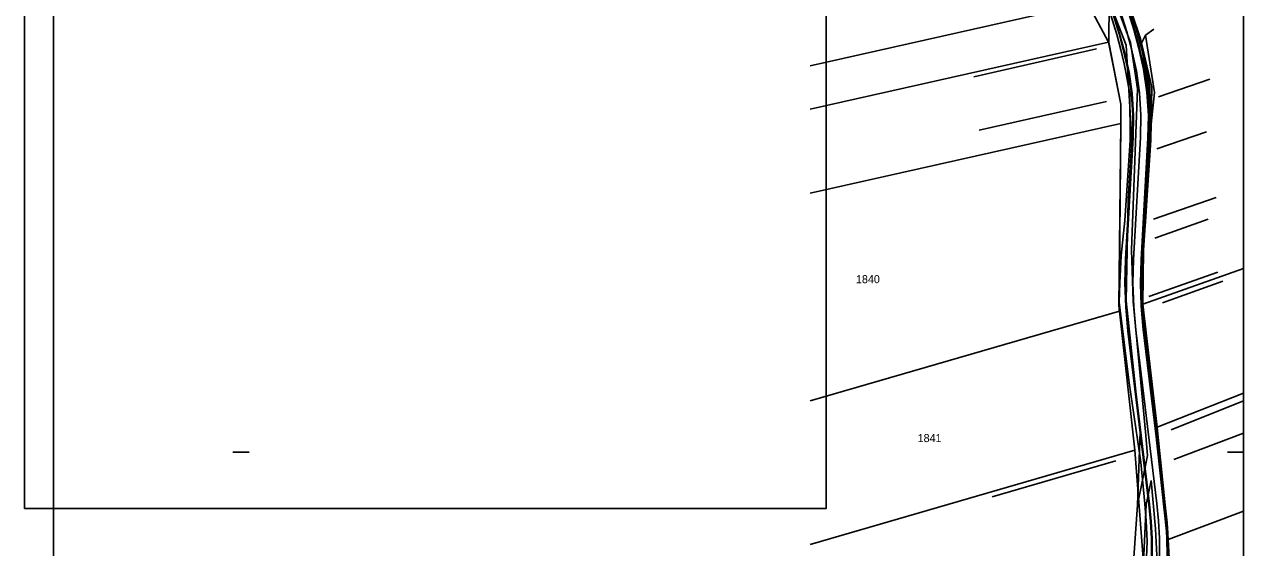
# Model space of a CAD drawing. Extents: x -601800 to -601487, y -1201912 to -1200862.
# Drawn here: x -601790.9 to -601486.7, y -1201516.2 to -1201385.7 of the extents above; entities that cross this region are included whole.
import ezdxf

# ---------------------------------------------------------------- set-up
doc = ezdxf.new("R2010")
doc.units = 0
for name, color, linetype in [('Hranice parcel', 7, 'Continuous'), ('Parcelní čísla', 7, 'Continuous'), ('u_hrany', 7, 'Continuous'), ('u_návrh', 7, 'Continuous'), ('u_osa', 7, 'Continuous'), ('u_strom', 7, 'Continuous'), ('u_terénní úpravy', 7, 'Continuous'), ('x_rám', 7, 'Continuous')]:
    doc.layers.add(name, color=color, linetype=linetype)

msp = doc.modelspace()

# ---------------------------------------------------------------- linework, layer by layer
at = {"layer": 'Hranice parcel'}
for p, q in [((-601594.83, -1201396.03), (-601525.57, -1201380.51)), ((-601525.57, -1201380.51), (-601520.35, -1201390.13)), ((-601594.83, -1201406.82), (-601520.35, -1201390.13)), ((-601594.83, -1201427.76), (-601517.31, -1201410.46)), ((-601594.83, -1201479.55), (-601517.67, -1201457.2)), ((-601517.67, -1201457.2), (-601513.82, -1201491.91)), ((-601508.25, -1201486.13), (-601511.82, -1201455.51)), ((-601594.83, -1201515.38), (-601513.82, -1201491.91)), ((-601513.82, -1201491.91), (-601511.75, -1201518.89)), ((-601486.66, -1201507.11), (-601505.47, -1201514.18))]:
    msp.add_line(p, q, dxfattribs=at)
for points in [[(-601511.82, -1201455.51), (-601511.63, -1201442.04), (-601509.82, -1201414.6), (-601509.57, -1201401.34), (-601512.41, -1201389.28), (-601514.66, -1201382.62)], [(-601520.35, -1201390.13), (-601517.26, -1201405.61), (-601517.31, -1201410.46)], [(-601517.31, -1201410.46), (-601517.81, -1201455.91), (-601517.67, -1201457.2)], [(-601486.66, -1201446.59), (-601511.82, -1201455.51)], [(-601486.66, -1201477.68), (-601508.25, -1201486.13)], [(-601505.47, -1201514.18), (-601505.62, -1201511.23), (-601508.14, -1201487.04), (-601508.25, -1201486.13)], [(-601504.99, -1201526.96), (-601504.94, -1201524.87), (-601505.47, -1201514.18)]]:
    msp.add_lwpolyline(points, dxfattribs=at)
at = {"layer": 'u_hrany'}
for points in [[(-601510.66, -1201493.25), (-601511.13, -1201487.34), (-601514.2, -1201454.81), (-601514.64, -1201441.92), (-601513.13, -1201401.75), (-601514.86, -1201390.2), (-601518.87, -1201379.54), (-601520.9, -1201374.92)], [(-601517.26, -1201405.61), (-601520.32, -1201390.19), (-601520.24, -1201380), (-601515.97, -1201390.87)], [(-601512.26, -1201390.52), (-601511.11, -1201388.4), (-601509.06, -1201386.94)], [(-601510.09, -1201413.72), (-601508.92, -1201402.68), (-601511.11, -1201388.4)], [(-601515.97, -1201390.87), (-601514.58, -1201414.64), (-601515.47, -1201429.34), (-601515.96, -1201454.63), (-601512.47, -1201487.32), (-601513.15, -1201505.52)], [(-601512.26, -1201390.52), (-601510.47, -1201401.41), (-601510.09, -1201413.72), (-601511.79, -1201441.97), (-601511.82, -1201455.52), (-601508.66, -1201487.01), (-601505.94, -1201512.07), (-601505.14, -1201523.95), (-601505.37, -1201547.09), (-601506.1, -1201561.67), (-601507, -1201580.71), (-601507.44, -1201612.51), (-601506.59, -1201624.18), (-601504.84, -1201632.93)], [(-601523.39, -1201391.84), (-601553.96, -1201398.76)], [(-601507.87, -1201403.76), (-601495.07, -1201399.33)], [(-601520.87, -1201404.96), (-601552.65, -1201412.05)], [(-601517.26, -1201410.36), (-601517.73, -1201457.2)], [(-601508.3, -1201416.7), (-601495.96, -1201412.46)], [(-601509.14, -1201434.24), (-601493.54, -1201428.85)], [(-601508.78, -1201439.01), (-601495.5, -1201434.28)], [(-601510.28, -1201453.55), (-601493.09, -1201447.49)], [(-601506.87, -1201455.17), (-601491.82, -1201449.78)], [(-601504.71, -1201486.78), (-601486.66, -1201479.62)], [(-601504.1, -1201494.18), (-601486.66, -1201487.68)], [(-601518.55, -1201494.53), (-601549.39, -1201503.49)], [(-601510.66, -1201493.25), (-601513.15, -1201505.52)], [(-601511, -1201505.42), (-601509.72, -1201499.44)], [(-601509.48, -1201566.66), (-601507.81, -1201547.43), (-601507.95, -1201524.83), (-601508.61, -1201511.46), (-601509.72, -1201499.44)], [(-601514.34, -1201522.2), (-601513.15, -1201505.52)], [(-601511, -1201505.42), (-601511.8, -1201523.53)]]:
    msp.add_lwpolyline(points, dxfattribs=at)
at = {"layer": 'u_návrh'}
for points in [[(-601553.14, -1201317.8), (-601552.81, -1201318.66), (-601546.01, -1201333.72), (-601538.39, -1201348.39), (-601530, -1201362.6), (-601525.72, -1201369.43), (-601523.16, -1201373.86), (-601520.96, -1201378.43), (-601519.1, -1201383.16), (-601517.59, -1201388.04), (-601516.46, -1201392.25), (-601515.25, -1201397.59), (-601514.48, -1201402.97), (-601514.13, -1201408.4), (-601514.23, -1201413.88), (-601515.96, -1201444.23), (-601516.12, -1201450.21), (-601515.93, -1201456.22), (-601515.39, -1201462.18), (-601510.17, -1201505.36), (-601509.75, -1201509.65), (-601509.52, -1201513.93), (-601509.47, -1201518.24), (-601509.71, -1201540.62)], [(-601549.75, -1201316.3), (-601549.39, -1201317.23), (-601542.68, -1201332.11), (-601535.16, -1201346.59), (-601526.84, -1201360.67), (-601522.55, -1201367.52), (-601519.89, -1201372.13), (-601517.56, -1201376.95), (-601515.6, -1201381.93), (-601514.03, -1201387.02), (-601512.87, -1201391.36), (-601511.61, -1201396.91), (-601510.79, -1201402.59), (-601510.43, -1201408.32), (-601510.53, -1201414.01), (-601512.26, -1201444.39), (-601512.42, -1201450.21), (-601512.24, -1201456), (-601511.71, -1201461.79), (-601506.5, -1201504.96), (-601506.06, -1201509.37), (-601505.82, -1201513.81), (-601505.77, -1201518.24), (-601506.19, -1201556.5)], [(-601515.46, -1201381.89), (-601513.89, -1201386.98), (-601512.72, -1201391.32), (-601511.46, -1201396.89), (-601510.64, -1201402.58), (-601510.28, -1201408.31), (-601510.38, -1201414.02), (-601512.11, -1201444.4), (-601512.27, -1201450.21), (-601512.09, -1201455.99), (-601511.56, -1201461.78), (-601506.35, -1201504.94), (-601505.91, -1201509.36), (-601505.67, -1201513.81), (-601505.62, -1201518.24), (-601506.04, -1201556.51)], [(-601519.24, -1201383.21), (-601517.73, -1201388.09), (-601516.61, -1201392.28), (-601515.4, -1201397.61), (-601514.63, -1201402.99), (-601514.28, -1201408.41), (-601514.38, -1201413.87), (-601516.11, -1201444.23), (-601516.27, -1201450.21), (-601516.08, -1201456.23), (-601515.54, -1201462.2), (-601510.32, -1201505.38), (-601509.9, -1201509.66), (-601509.67, -1201513.94), (-601509.62, -1201518.24), (-601509.86, -1201540.61)]]:
    msp.add_lwpolyline(points, dxfattribs=at)
at = {"layer": 'u_osa'}
msp.add_lwpolyline([(-601517.35, -1201382.55), (-601515.81, -1201387.53), (-601514.66, -1201391.8), (-601513.43, -1201397.25), (-601512.63, -1201402.78), (-601512.28, -1201408.36), (-601512.38, -1201413.95), (-601514.11, -1201444.31), (-601514.27, -1201450.21), (-601514.08, -1201456.11), (-601513.55, -1201461.99), (-601508.33, -1201505.16), (-601507.91, -1201509.51), (-601507.67, -1201513.87), (-601507.62, -1201518.24), (-601508.04, -1201556.38), (-601508.4, -1201559.4), (-601509.41, -1201562.27), (-601511.01, -1201564.85), (-601513.14, -1201567.02), (-601515.68, -1201568.69), (-601576.3, -1201599.45)], dxfattribs=at)
at = {"layer": 'u_strom'}
msp.add_lwpolyline([(-601790.89, -1201506.46), (-601590.84, -1201506.46), (-601590.84, -1201327.83), (-601790.89, -1201327.83)], close=True, dxfattribs=at)
at = {"layer": 'u_terénní úpravy'}
for points in [[(-601515.18, -1201381.79), (-601513.5, -1201386.77), (-601512.27, -1201391.07), (-601511.36, -1201394.46), (-601510.89, -1201396.94), (-601510.1, -1201401.3), (-601509.88, -1201408.41), (-601509.86, -1201414.92), (-601511.16, -1201434.93), (-601511.79, -1201442.27), (-601511.95, -1201449.35), (-601511.81, -1201454.7), (-601511.82, -1201455.51), (-601511.2, -1201461.7), (-601509.62, -1201474.39), (-601508.62, -1201486.14), (-601507.39, -1201494.24), (-601506.28, -1201504.86), (-601505.75, -1201510), (-601505.46, -1201514.4), (-601505.14, -1201523.95), (-601505.17, -1201535.09), (-601505.65, -1201556.08), (-601506.35, -1201585.45)], [(-601519.79, -1201383.4), (-601518.29, -1201388.25), (-601517.27, -1201392.04), (-601516.45, -1201395.57), (-601515.96, -1201398.02), (-601515.07, -1201403.03), (-601514.93, -1201414.63), (-601514.93, -1201414.63), (-601516.33, -1201434.63), (-601517.23, -1201443.32), (-601517.51, -1201450.18), (-601517.73, -1201454.99), (-601515.19, -1201475.06), (-601512.31, -1201494.84), (-601511.29, -1201505.25), (-601511, -1201509.5), (-601510.74, -1201514.55), (-601511.19, -1201526.6)]]:
    msp.add_lwpolyline(points, dxfattribs=at)
at = {"layer": 'x_rám'}
for p, q in [((-601734.8, -1201492.35), (-601738.84, -1201492.35)), ((-601486.66, -1201492.35), (-601490.7, -1201492.35))]:
    msp.add_line(p, q, dxfattribs=at)
msp.add_lwpolyline([(-601486.66, -1200862.35), (-601486.66, -1201912.35), (-601783.66, -1201912.35), (-601783.66, -1200862.35)], close=True, dxfattribs=at)

# ---------------------------------------------------------------- texts
at = {"layer": 'Parcelní čísla'}
for s, p in [('1840', (-601583.38, -1201450.24)), ('1841', (-601568, -1201489.87))]:
    msp.add_text(s, height=2, dxfattribs=at).set_placement(p)

doc.saveas('drawing.dxf')
